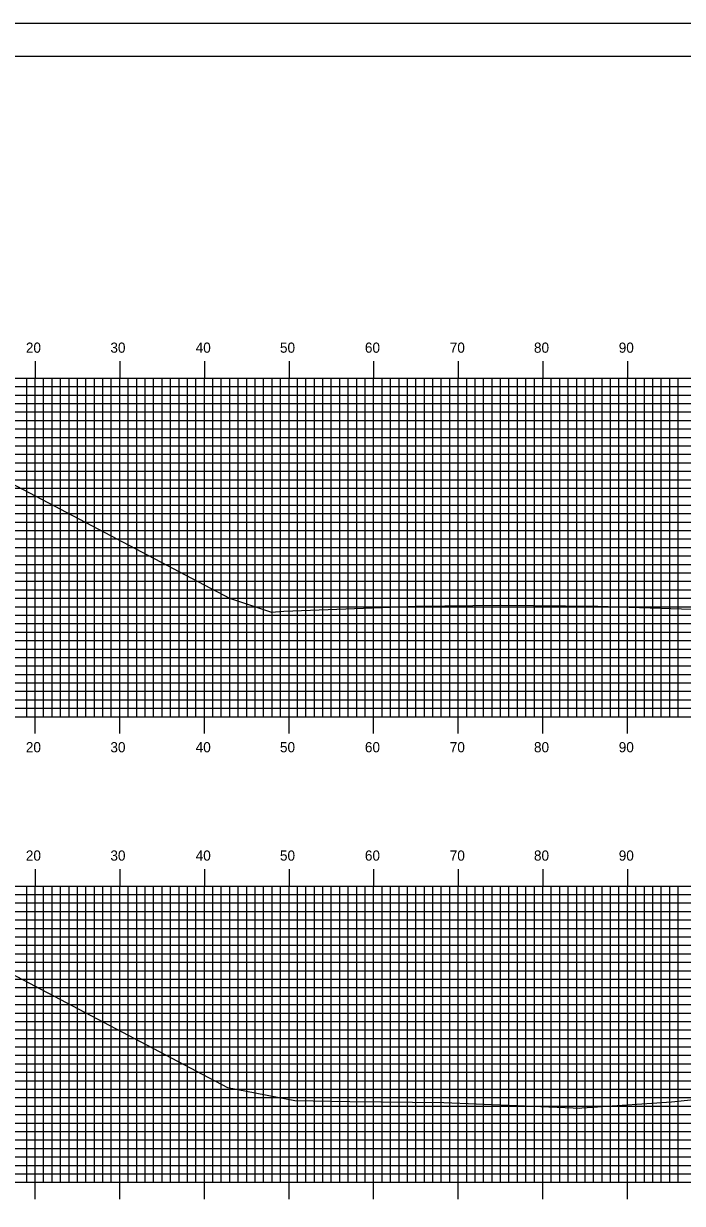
# Model space of a CAD drawing. Extents: x 850966 to 851310, y 364661 to 364881.
# Drawn here: x 851150.9 to 851228.7, y 364741.9 to 364881.3 of the extents above; entities that cross this region are included whole.
import ezdxf

# ---------------------------------------------------------------- set-up
doc = ezdxf.new("R2010")
doc.units = 0
for name, color, linetype in [('BORDER', 7, 'Continuous'), ('H_V ANNOTATION', 7, 'Continuous'), ('MAJOR', 7, 'Continuous'), ('MINOR', 7, 'Continuous'), ('PLOT BOUNDARY', 7, 'Continuous'), ('S_Roadway_Centerline', 7, 'Continuous')]:
    doc.layers.add(name, color=color, linetype=linetype)

msp = doc.modelspace()

# ---------------------------------------------------------------- linework, layer by layer
at = {"layer": 'BORDER'}
msp.add_lwpolyline([(850982.62, 364667.37), (851302.62, 364667.37), (851302.62, 364877.37), (850982.62, 364877.37)], close=True, dxfattribs=at)
at = {"layer": 'MAJOR'}
for p, q in [((851152.22, 364841.37), (851152.22, 364839.37)), ((851162.22, 364841.37), (851162.22, 364839.37)), ((851172.22, 364841.37), (851172.22, 364839.37)), ((851182.22, 364841.37), (851182.22, 364839.37)), ((851192.22, 364841.37), (851192.22, 364839.37)), ((851202.22, 364841.37), (851202.22, 364839.37)), ((851212.22, 364841.37), (851212.22, 364839.37)), ((851222.22, 364841.37), (851222.22, 364839.37)), ((850992.22, 364839.37), (851272.22, 364839.37)), ((850992.22, 364839.37), (851272.22, 364839.37)), ((851152.22, 364799.37), (851152.22, 364839.37)), ((851162.22, 364799.37), (851162.22, 364839.37)), ((851172.22, 364799.37), (851172.22, 364839.37)), ((851182.22, 364799.37), (851182.22, 364839.37)), ((851192.22, 364799.37), (851192.22, 364839.37)), ((851202.22, 364799.37), (851202.22, 364839.37)), ((851212.22, 364799.37), (851212.22, 364839.37)), ((851222.22, 364799.37), (851222.22, 364839.37)), ((850992.22, 364834.37), (851272.22, 364834.37)), ((850992.22, 364829.37), (851272.22, 364829.37)), ((850992.22, 364824.37), (851272.22, 364824.37)), ((850992.22, 364819.37), (851272.22, 364819.37)), ((850992.22, 364814.37), (851272.22, 364814.37)), ((850992.22, 364809.37), (851272.22, 364809.37)), ((850992.22, 364804.37), (851272.22, 364804.37)), ((850992.22, 364799.37), (851272.22, 364799.37)), ((850992.22, 364799.37), (851272.22, 364799.37)), ((851152.22, 364797.37), (851152.22, 364799.37)), ((851162.22, 364797.37), (851162.22, 364799.37)), ((851172.22, 364797.37), (851172.22, 364799.37)), ((851182.22, 364797.37), (851182.22, 364799.37)), ((851192.22, 364797.37), (851192.22, 364799.37)), ((851202.22, 364797.37), (851202.22, 364799.37)), ((851212.22, 364797.37), (851212.22, 364799.37)), ((851222.22, 364797.37), (851222.22, 364799.37)), ((851152.22, 364781.37), (851152.22, 364779.37)), ((851162.22, 364781.37), (851162.22, 364779.37)), ((851172.22, 364781.37), (851172.22, 364779.37)), ((851182.22, 364781.37), (851182.22, 364779.37)), ((851192.22, 364781.37), (851192.22, 364779.37)), ((851202.22, 364781.37), (851202.22, 364779.37)), ((851212.22, 364781.37), (851212.22, 364779.37)), ((851222.22, 364781.37), (851222.22, 364779.37)), ((850992.22, 364779.37), (851272.22, 364779.37)), ((850992.22, 364779.37), (851272.22, 364779.37)), ((851152.22, 364744.37), (851152.22, 364779.37)), ((851162.22, 364744.37), (851162.22, 364779.37)), ((851172.22, 364744.37), (851172.22, 364779.37)), ((851182.22, 364744.37), (851182.22, 364779.37)), ((851192.22, 364744.37), (851192.22, 364779.37)), ((851202.22, 364744.37), (851202.22, 364779.37)), ((851212.22, 364744.37), (851212.22, 364779.37)), ((851222.22, 364744.37), (851222.22, 364779.37)), ((850992.22, 364774.37), (851272.22, 364774.37)), ((850992.22, 364769.37), (851272.22, 364769.37)), ((850992.22, 364764.37), (851272.22, 364764.37)), ((850992.22, 364759.37), (851272.22, 364759.37)), ((850992.22, 364754.37), (851272.22, 364754.37)), ((850992.22, 364749.37), (851272.22, 364749.37)), ((850992.22, 364744.37), (851272.22, 364744.37)), ((850992.22, 364744.37), (851272.22, 364744.37)), ((851152.22, 364742.37), (851152.22, 364744.37)), ((851162.22, 364742.37), (851162.22, 364744.37)), ((851172.22, 364742.37), (851172.22, 364744.37)), ((851182.22, 364742.37), (851182.22, 364744.37)), ((851192.22, 364742.37), (851192.22, 364744.37)), ((851202.22, 364742.37), (851202.22, 364744.37)), ((851212.22, 364742.37), (851212.22, 364744.37)), ((851222.22, 364742.37), (851222.22, 364744.37))]:
    msp.add_line(p, q, dxfattribs=at)
at = {"layer": 'MINOR'}
for p, q in [((851151.22, 364799.37), (851151.22, 364839.37)), ((851153.22, 364799.37), (851153.22, 364839.37)), ((851154.22, 364799.37), (851154.22, 364839.37)), ((851155.22, 364799.37), (851155.22, 364839.37)), ((851156.22, 364799.37), (851156.22, 364839.37)), ((851157.22, 364799.37), (851157.22, 364839.37)), ((851158.22, 364799.37), (851158.22, 364839.37)), ((851159.22, 364799.37), (851159.22, 364839.37)), ((851160.22, 364799.37), (851160.22, 364839.37)), ((851161.22, 364799.37), (851161.22, 364839.37)), ((851163.22, 364799.37), (851163.22, 364839.37)), ((851164.22, 364799.37), (851164.22, 364839.37)), ((851165.22, 364799.37), (851165.22, 364839.37)), ((851166.22, 364799.37), (851166.22, 364839.37)), ((851167.22, 364799.37), (851167.22, 364839.37)), ((851168.22, 364799.37), (851168.22, 364839.37)), ((851169.22, 364799.37), (851169.22, 364839.37)), ((851170.22, 364799.37), (851170.22, 364839.37)), ((851171.22, 364799.37), (851171.22, 364839.37)), ((851173.22, 364799.37), (851173.22, 364839.37)), ((851174.22, 364799.37), (851174.22, 364839.37)), ((851175.22, 364799.37), (851175.22, 364839.37)), ((851176.22, 364799.37), (851176.22, 364839.37)), ((851177.22, 364799.37), (851177.22, 364839.37)), ((851178.22, 364799.37), (851178.22, 364839.37)), ((851179.22, 364799.37), (851179.22, 364839.37)), ((851180.22, 364799.37), (851180.22, 364839.37)), ((851181.22, 364799.37), (851181.22, 364839.37)), ((851183.22, 364799.37), (851183.22, 364839.37)), ((851184.22, 364799.37), (851184.22, 364839.37)), ((851185.22, 364799.37), (851185.22, 364839.37)), ((851186.22, 364799.37), (851186.22, 364839.37)), ((851187.22, 364799.37), (851187.22, 364839.37)), ((851188.22, 364799.37), (851188.22, 364839.37)), ((851189.22, 364799.37), (851189.22, 364839.37)), ((851190.22, 364799.37), (851190.22, 364839.37)), ((851191.22, 364799.37), (851191.22, 364839.37)), ((851193.22, 364799.37), (851193.22, 364839.37)), ((851194.22, 364799.37), (851194.22, 364839.37)), ((851195.22, 364799.37), (851195.22, 364839.37)), ((851196.22, 364799.37), (851196.22, 364839.37)), ((851197.22, 364799.37), (851197.22, 364839.37)), ((851198.22, 364799.37), (851198.22, 364839.37)), ((851199.22, 364799.37), (851199.22, 364839.37)), ((851200.22, 364799.37), (851200.22, 364839.37)), ((851201.22, 364799.37), (851201.22, 364839.37)), ((851203.22, 364799.37), (851203.22, 364839.37)), ((851204.22, 364799.37), (851204.22, 364839.37)), ((851205.22, 364799.37), (851205.22, 364839.37)), ((851206.22, 364799.37), (851206.22, 364839.37)), ((851207.22, 364799.37), (851207.22, 364839.37)), ((851208.22, 364799.37), (851208.22, 364839.37)), ((851209.22, 364799.37), (851209.22, 364839.37)), ((851210.22, 364799.37), (851210.22, 364839.37)), ((851211.22, 364799.37), (851211.22, 364839.37)), ((851213.22, 364799.37), (851213.22, 364839.37)), ((851214.22, 364799.37), (851214.22, 364839.37)), ((851215.22, 364799.37), (851215.22, 364839.37)), ((851216.22, 364799.37), (851216.22, 364839.37)), ((851217.22, 364799.37), (851217.22, 364839.37)), ((851218.22, 364799.37), (851218.22, 364839.37)), ((851219.22, 364799.37), (851219.22, 364839.37)), ((851220.22, 364799.37), (851220.22, 364839.37)), ((851221.22, 364799.37), (851221.22, 364839.37)), ((851223.22, 364799.37), (851223.22, 364839.37)), ((851224.22, 364799.37), (851224.22, 364839.37)), ((851225.22, 364799.37), (851225.22, 364839.37)), ((851226.22, 364799.37), (851226.22, 364839.37)), ((851227.22, 364799.37), (851227.22, 364839.37)), ((851228.22, 364799.37), (851228.22, 364839.37)), ((850992.22, 364838.37), (851272.22, 364838.37)), ((850992.22, 364837.37), (851272.22, 364837.37)), ((850992.22, 364836.37), (851272.22, 364836.37)), ((850992.22, 364835.37), (851272.22, 364835.37)), ((850992.22, 364833.37), (851272.22, 364833.37)), ((850992.22, 364832.37), (851272.22, 364832.37)), ((850992.22, 364831.37), (851272.22, 364831.37)), ((850992.22, 364830.37), (851272.22, 364830.37)), ((850992.22, 364828.37), (851272.22, 364828.37)), ((850992.22, 364827.37), (851272.22, 364827.37)), ((850992.22, 364826.37), (851272.22, 364826.37)), ((850992.22, 364825.37), (851272.22, 364825.37)), ((850992.22, 364823.37), (851272.22, 364823.37)), ((850992.22, 364822.37), (851272.22, 364822.37)), ((850992.22, 364821.37), (851272.22, 364821.37)), ((850992.22, 364820.37), (851272.22, 364820.37)), ((850992.22, 364818.37), (851272.22, 364818.37)), ((850992.22, 364817.37), (851272.22, 364817.37)), ((850992.22, 364816.37), (851272.22, 364816.37)), ((850992.22, 364815.37), (851272.22, 364815.37)), ((850992.22, 364813.37), (851272.22, 364813.37)), ((850992.22, 364812.37), (851272.22, 364812.37)), ((850992.22, 364811.37), (851272.22, 364811.37)), ((850992.22, 364810.37), (851272.22, 364810.37)), ((850992.22, 364808.37), (851272.22, 364808.37)), ((850992.22, 364807.37), (851272.22, 364807.37)), ((850992.22, 364806.37), (851272.22, 364806.37)), ((850992.22, 364805.37), (851272.22, 364805.37)), ((850992.22, 364803.37), (851272.22, 364803.37)), ((850992.22, 364802.37), (851272.22, 364802.37)), ((850992.22, 364801.37), (851272.22, 364801.37)), ((850992.22, 364800.37), (851272.22, 364800.37)), ((851151.22, 364744.37), (851151.22, 364779.37)), ((851153.22, 364744.37), (851153.22, 364779.37)), ((851154.22, 364744.37), (851154.22, 364779.37)), ((851155.22, 364744.37), (851155.22, 364779.37)), ((851156.22, 364744.37), (851156.22, 364779.37)), ((851157.22, 364744.37), (851157.22, 364779.37)), ((851158.22, 364744.37), (851158.22, 364779.37)), ((851159.22, 364744.37), (851159.22, 364779.37)), ((851160.22, 364744.37), (851160.22, 364779.37)), ((851161.22, 364744.37), (851161.22, 364779.37)), ((851163.22, 364744.37), (851163.22, 364779.37)), ((851164.22, 364744.37), (851164.22, 364779.37)), ((851165.22, 364744.37), (851165.22, 364779.37)), ((851166.22, 364744.37), (851166.22, 364779.37)), ((851167.22, 364744.37), (851167.22, 364779.37)), ((851168.22, 364744.37), (851168.22, 364779.37)), ((851169.22, 364744.37), (851169.22, 364779.37)), ((851170.22, 364744.37), (851170.22, 364779.37)), ((851171.22, 364744.37), (851171.22, 364779.37)), ((851173.22, 364744.37), (851173.22, 364779.37)), ((851174.22, 364744.37), (851174.22, 364779.37)), ((851175.22, 364744.37), (851175.22, 364779.37)), ((851176.22, 364744.37), (851176.22, 364779.37)), ((851177.22, 364744.37), (851177.22, 364779.37)), ((851178.22, 364744.37), (851178.22, 364779.37)), ((851179.22, 364744.37), (851179.22, 364779.37)), ((851180.22, 364744.37), (851180.22, 364779.37)), ((851181.22, 364744.37), (851181.22, 364779.37)), ((851183.22, 364744.37), (851183.22, 364779.37)), ((851184.22, 364744.37), (851184.22, 364779.37)), ((851185.22, 364744.37), (851185.22, 364779.37)), ((851186.22, 364744.37), (851186.22, 364779.37)), ((851187.22, 364744.37), (851187.22, 364779.37)), ((851188.22, 364744.37), (851188.22, 364779.37)), ((851189.22, 364744.37), (851189.22, 364779.37)), ((851190.22, 364744.37), (851190.22, 364779.37)), ((851191.22, 364744.37), (851191.22, 364779.37)), ((851193.22, 364744.37), (851193.22, 364779.37)), ((851194.22, 364744.37), (851194.22, 364779.37)), ((851195.22, 364744.37), (851195.22, 364779.37)), ((851196.22, 364744.37), (851196.22, 364779.37)), ((851197.22, 364744.37), (851197.22, 364779.37)), ((851198.22, 364744.37), (851198.22, 364779.37)), ((851199.22, 364744.37), (851199.22, 364779.37)), ((851200.22, 364744.37), (851200.22, 364779.37)), ((851201.22, 364744.37), (851201.22, 364779.37)), ((851203.22, 364744.37), (851203.22, 364779.37)), ((851204.22, 364744.37), (851204.22, 364779.37)), ((851205.22, 364744.37), (851205.22, 364779.37)), ((851206.22, 364744.37), (851206.22, 364779.37)), ((851207.22, 364744.37), (851207.22, 364779.37)), ((851208.22, 364744.37), (851208.22, 364779.37)), ((851209.22, 364744.37), (851209.22, 364779.37)), ((851210.22, 364744.37), (851210.22, 364779.37)), ((851211.22, 364744.37), (851211.22, 364779.37)), ((851213.22, 364744.37), (851213.22, 364779.37)), ((851214.22, 364744.37), (851214.22, 364779.37)), ((851215.22, 364744.37), (851215.22, 364779.37)), ((851216.22, 364744.37), (851216.22, 364779.37)), ((851217.22, 364744.37), (851217.22, 364779.37)), ((851218.22, 364744.37), (851218.22, 364779.37)), ((851219.22, 364744.37), (851219.22, 364779.37)), ((851220.22, 364744.37), (851220.22, 364779.37)), ((851221.22, 364744.37), (851221.22, 364779.37)), ((851223.22, 364744.37), (851223.22, 364779.37)), ((851224.22, 364744.37), (851224.22, 364779.37)), ((851225.22, 364744.37), (851225.22, 364779.37)), ((851226.22, 364744.37), (851226.22, 364779.37)), ((851227.22, 364744.37), (851227.22, 364779.37)), ((851228.22, 364744.37), (851228.22, 364779.37)), ((850992.22, 364778.37), (851272.22, 364778.37)), ((850992.22, 364777.37), (851272.22, 364777.37)), ((850992.22, 364776.37), (851272.22, 364776.37)), ((850992.22, 364775.37), (851272.22, 364775.37)), ((850992.22, 364773.37), (851272.22, 364773.37)), ((850992.22, 364772.37), (851272.22, 364772.37)), ((850992.22, 364771.37), (851272.22, 364771.37)), ((850992.22, 364770.37), (851272.22, 364770.37)), ((850992.22, 364768.37), (851272.22, 364768.37)), ((850992.22, 364767.37), (851272.22, 364767.37)), ((850992.22, 364766.37), (851272.22, 364766.37)), ((850992.22, 364765.37), (851272.22, 364765.37)), ((850992.22, 364763.37), (851272.22, 364763.37)), ((850992.22, 364762.37), (851272.22, 364762.37)), ((850992.22, 364761.37), (851272.22, 364761.37)), ((850992.22, 364760.37), (851272.22, 364760.37)), ((850992.22, 364758.37), (851272.22, 364758.37)), ((850992.22, 364757.37), (851272.22, 364757.37)), ((850992.22, 364756.37), (851272.22, 364756.37)), ((850992.22, 364755.37), (851272.22, 364755.37)), ((850992.22, 364753.37), (851272.22, 364753.37)), ((850992.22, 364752.37), (851272.22, 364752.37)), ((850992.22, 364751.37), (851272.22, 364751.37)), ((850992.22, 364750.37), (851272.22, 364750.37)), ((850992.22, 364748.37), (851272.22, 364748.37)), ((850992.22, 364747.37), (851272.22, 364747.37)), ((850992.22, 364746.37), (851272.22, 364746.37)), ((850992.22, 364745.37), (851272.22, 364745.37))]:
    msp.add_line(p, q, dxfattribs=at)
at = {"layer": 'PLOT BOUNDARY'}
msp.add_lwpolyline([(850966.43, 364661.25), (851306.43, 364661.25), (851306.43, 364881.25), (850966.43, 364881.25)], close=True, dxfattribs=at)
at = {"layer": 'S_Roadway_Centerline'}
for points in [[(851095.7, 364826.78), (851100.01, 364828.93), (851105.22, 364831.53), (851108.22, 364831.59), (851116.22, 364831.75), (851132.22, 364830.83), (851140.22, 364830.36), (851143.22, 364830.19), (851148.55, 364827.38), (851175.19, 364813.36)], [(851175.19, 364813.36), (851180.02, 364811.75), (851180.13, 364811.73), (851181.59, 364811.83), (851197.27, 364812.43), (851207.28, 364812.55), (851218.7, 364812.43), (851229.81, 364812.08), (851230.74, 364812), (851239.29, 364813.12), (851247.66, 364813.95), (851257.85, 364814.29), (851265.31, 364814.74), (851270.85, 364815.07), (851272.22, 364815.2)], [(851100.01, 364771.02), (851100.03, 364771.03), (851105.22, 364773.63), (851108.22, 364773.69), (851116.22, 364773.85), (851132.22, 364772.92), (851140.22, 364772.46), (851143.22, 364772.28), (851148.55, 364769.47), (851174.97, 364755.57)], [(851174.97, 364755.57), (851182.92, 364754.02), (851189.42, 364753.91), (851200.51, 364753.81), (851215.81, 364753.16), (851216.58, 364753.13), (851216.84, 364753.15), (851218.07, 364753.25), (851227.43, 364753.86), (851232.7, 364754.44), (851236.72, 364754.71), (851244.84, 364755.03), (851255.04, 364755.34), (851258.64, 364755.43), (851266.41, 364756.05), (851270.58, 364756.32), (851272.22, 364756.39)]]:
    msp.add_lwpolyline(points, dxfattribs=at)

# ---------------------------------------------------------------- texts
at = {"layer": 'H_V ANNOTATION'}
for s, p in [('20', (851151.12, 364842.37)), ('30', (851161.11, 364842.37)), ('40', (851171.19, 364842.37)), ('50', (851181.15, 364842.37)), ('60', (851191.19, 364842.37)), ('70', (851201.22, 364842.37)), ('80', (851211.17, 364842.37)), ('90', (851221.19, 364842.37)), ('20', (851151.12, 364795.17)), ('30', (851161.11, 364795.17)), ('40', (851171.19, 364795.17)), ('50', (851181.15, 364795.17)), ('60', (851191.19, 364795.17)), ('70', (851201.22, 364795.17)), ('80', (851211.17, 364795.17)), ('90', (851221.19, 364795.17)), ('20', (851151.12, 364782.37)), ('30', (851161.11, 364782.37)), ('40', (851171.19, 364782.37)), ('50', (851181.15, 364782.37)), ('60', (851191.19, 364782.37)), ('70', (851201.22, 364782.37)), ('80', (851211.17, 364782.37)), ('90', (851221.19, 364782.37))]:
    msp.add_text(s, height=1.2, dxfattribs=at).set_placement(p)

doc.saveas('drawing.dxf')
